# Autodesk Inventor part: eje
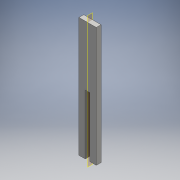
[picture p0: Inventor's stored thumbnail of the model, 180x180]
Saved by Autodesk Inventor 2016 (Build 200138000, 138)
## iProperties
Created: 2016-06
Part Number: eje
Material: Genérico
Document SubType Name: Modeling
Designer: adm
Density: 1 g/cm^3
Appearance: Valor por defecto
Author: adm
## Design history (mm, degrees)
sketch "Boceto1"
  geometry: L1 (-7.25, -2)-(7.25, -2); L2 (7.25, -2)-(7.25, 2); L3 (7.25, 2)-(-7.25, 2); L4 (-7.25, 2)-(-7.25, -2); L5 (-7.25, -2)-(7.25, 2); L6 (7.25, -2)-(-7.25, 2); 1 further point
  constraints: 12 end point, 2 midpoint, 2 parallel, 1 horizontal, 1 perpendicular
  dimensions: "d0" = 14.5 distance of L3.end L2.end; "d1" = 4 distance of L1.end L2.end
extrude "Extrusión1" new body sketch "Boceto1" distance "d2" = 100; taper "d3" = 0 deg
sketch "Boceto2"
  geometry: L1 (0, 0)-(14.5, 0) reference; L2 (5.25, 0)-(5.25, -50); L3 (5.25, -50)-(9.25, -50); L4 (9.25, -50)-(9.25, 0); L5 (5.25, 0)-(9.25, 0); L6 (0, 0)-(0, -100) reference; L7 (14.5, -100)-(0, -100) reference; 1 further point
  constraints: 8 end point, 2 perpendicular, 2 point on line, 1 collinear, 1 vertical
  dimensions: "d4" = 5.25 distance between parallel lines of L6 L2; "d5" = 4 distance between parallel lines of L4 L2; "d6" = 50 distance between parallel lines of L7 L3
extrude "Extrusión2" cut sketch "Boceto2" distance "d7" = 100; taper "d8" = 0 deg
node "Sólido1"
